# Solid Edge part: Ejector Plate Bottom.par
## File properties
Author: davee
Template: Normal.par
Last saved by: davee
Revision: 12
Application: Solid Edge
Accuracy: 0.990
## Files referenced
..\Loose Support Mould.asm
MH Insert3.par
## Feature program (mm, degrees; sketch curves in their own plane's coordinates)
sketch for "unnamed Protrusion 1" plane through (0, 0, 0) normal (0, 0, 1) x-axis (1, 0, 0)
  line (-62.5, -100) -> (62.5, -100)
  line (62.5, -100) -> (62.5, 100)
  line (62.5, 100) -> (-62.5, 100)
  line (-62.5, 100) -> (-62.5, -100)
  dimension (linear) = 62.5
  dimension (linear) = 62.5
extrude "unnamed Protrusion 1" add finite 16 along -normal
sketch for "Hole_1" plane through (0, 0, -16) normal (0, 0, -1) x-axis (1, 0, 0)
  hole centre (0, 0) bore radius 4.188
hole "Hole_1" finite  VBottomAngle = 118 deg; ThreadDepth = 2 mm
sketch for "Hole_2" plane through (0, 0, -16) normal (0, 0, -1) x-axis (-1, 0, 0)
  hole centre (-54, 89) bore radius 3.25
hole "Hole_2" diameter 6.5 through  CounterBoreDepth = 6.5 mm; VBottomAngle = 118 deg
sketch for "unnamed Hole 1" plane through (0, 0, -16) normal (0, 0, -1) x-axis (-1, 0, 0)
  hole centre (54, 89) bore radius 3.25
hole "unnamed Hole 1" through
sketch for "unnamed Hole 2" plane through (0, 0, -16) normal (0, 0, -1) x-axis (-1, 0, 0)
  hole centre (54, -89) bore radius 3.25
hole "unnamed Hole 2" through
sketch for "unnamed Hole 3" plane through (0, 0, -16) normal (0, 0, -1) x-axis (-1, 0, 0)
  hole centre (-54, -89) bore radius 3.25
hole "unnamed Hole 3" through
pattern "unnamed Pattern 1" of "Hole_2", "unnamed Hole 1", "unnamed Hole 2", "unnamed Hole 3"
sketch for "ExtrudedCutout_1" plane through (0, 0, 0) normal (0, 0, 1) x-axis (-1, 0, 0)
  circle centre (0, -95) radius 3
extrude "ExtrudedCutout_1" cut finite 41.275 along -normal
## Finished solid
Body 1: solid body, 21 faces, 33 edges, 8 vertices.
  Faces by surface: cylinder 10, plane 10, cone 1
  Edges by curve: circle 21, line 12
Bounding box of the edges (mm): 125.000 x 200.000 x 16.000, from (-62.5, -100, -16) to (62.5, 100, 0).
Cylindrical faces by radius (mm): R3 x1, R3.25 x4, R4.188 x1, R5.5 x4
Conical faces (half-angle, radius in mm at the cone's reference point): 59 deg R4.188 x1
Planar faces by outward normal: +x 1, +y 1, +z 1, -x 1, -y 1, -z 5
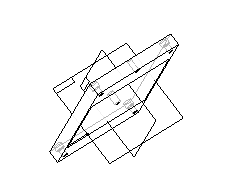
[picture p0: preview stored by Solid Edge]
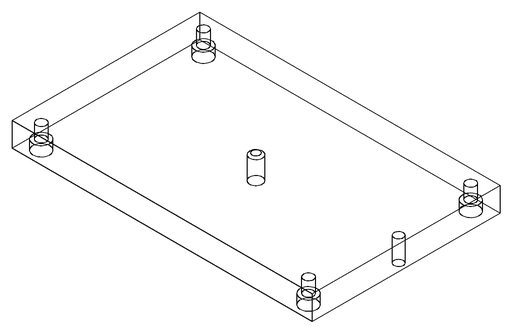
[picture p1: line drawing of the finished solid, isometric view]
